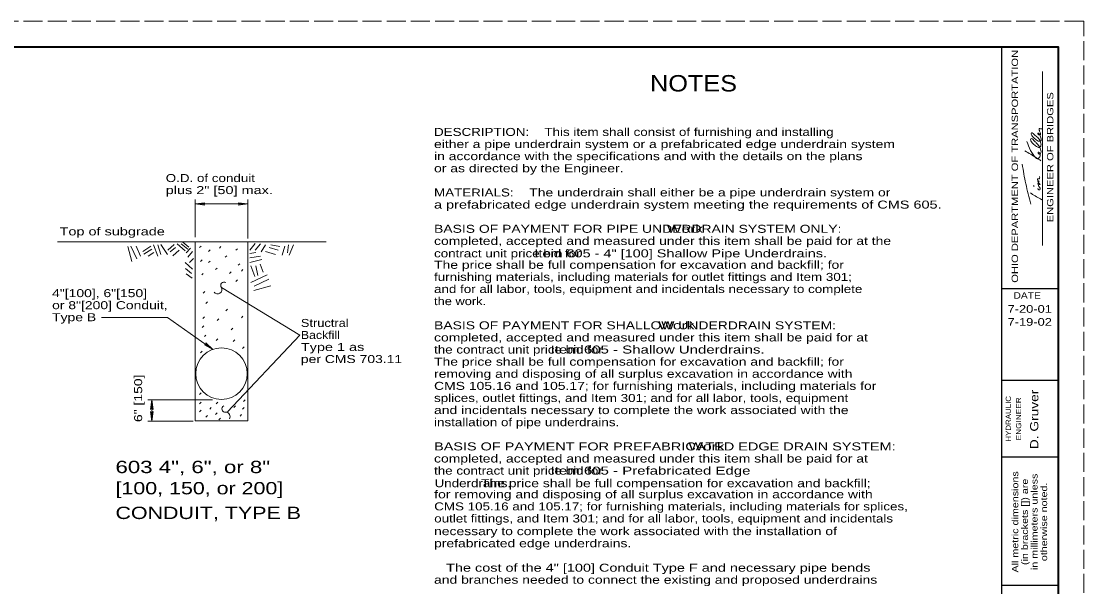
# Model space of a CAD drawing. Extents: x 743.9 to 777.9, y 1051 to 1073.
# Drawn here: x 757.15 to 777.86, y 1062 to 1073.02 of the extents above; entities that cross this region are included whole.
import ezdxf
from ezdxf.enums import TextEntityAlignment as Align

# ---------------------------------------------------------------- set-up
doc = ezdxf.new("R2010")
doc.units = 0
doc.header["$LTSCALE"] = 0.062
doc.linetypes.add('LONG_DASHED', pattern=[7.5, 6, -1.5])
doc.layers.add('1', color=7, linetype='Continuous', lineweight=13)
doc.layers.add('47', color=7, linetype='Continuous', lineweight=13)

msp = doc.modelspace()

# ---------------------------------------------------------------- linework, layer by layer
at = {"layer": '1', "lineweight": 25}
for p, q in [((745.86317, 1072.51808), (777.36317, 1072.51808)), ((776.26317, 1051.51808), (776.26317, 1072.51808)), ((777.36317, 1072.51808), (777.36317, 1051.51808)), ((777.36317, 1067.80225), (776.26317, 1067.80225)), ((777.36317, 1066.01808), (776.26317, 1066.01808)), ((777.36317, 1064.51808), (776.26317, 1064.51808)), ((777.36317, 1062.01808), (776.26317, 1062.01808))]:
    msp.add_line(p, q, dxfattribs=at)
at = {"layer": '1'}
for p, q in [((777.06192, 1068.64908), (777.06192, 1072.03917)), ((776.89442, 1069.8), (776.88425, 1069.81925)), ((760.54325, 1068.80992), (760.54325, 1069.54167)), ((761.56733, 1068.78375), (761.56733, 1069.54167)), ((760.54325, 1069.45808), (761.56733, 1069.45808)), ((757.85758, 1068.72042), (763.09308, 1068.72042)), ((760.54325, 1065.22875), (760.54325, 1068.72042)), ((761.56733, 1065.22875), (761.56733, 1068.72042)), ((759.31017, 1068.33375), (759.22658, 1068.6265)), ((759.40425, 1068.38608), (759.28925, 1068.63692)), ((759.47733, 1068.43833), (759.39375, 1068.63692)), ((759.67592, 1068.63692), (759.51917, 1068.53242)), ((759.69683, 1068.57425), (759.54008, 1068.48017)), ((759.73867, 1068.5115), (759.62367, 1068.43833)), ((759.81175, 1068.43833), (759.72817, 1068.65783)), ((759.8745, 1068.46967), (759.81175, 1068.65783)), ((759.99992, 1068.46967), (759.8745, 1068.66833)), ((760.13575, 1068.66833), (760.01033, 1068.55333)), ((760.15667, 1068.60558), (760.05217, 1068.52192)), ((760.22975, 1068.55333), (760.10442, 1068.44875)), ((760.34475, 1068.54283), (760.188, 1068.67875)), ((760.397, 1068.57425), (760.27158, 1068.67875)), ((760.41792, 1068.616), (760.30292, 1068.71017)), ((760.44925, 1068.59517), (760.36567, 1068.50108)), ((760.49108, 1068.53242), (760.397, 1068.41742)), ((760.65825, 1068.637), (760.62692, 1068.60558)), ((760.83592, 1068.56383), (760.80458, 1068.53242)), ((761.04492, 1068.6265), (761.01358, 1068.59508)), ((761.36892, 1068.58467), (761.33758, 1068.55325)), ((761.60925, 1068.55333), (761.71375, 1068.68925)), ((761.72417, 1068.5115), (761.60925, 1068.49058)), ((761.71375, 1068.55333), (761.81825, 1068.67875)), ((761.82867, 1068.52192), (761.91225, 1068.65783)), ((761.91225, 1068.53242), (762.11083, 1068.46967)), ((761.98542, 1068.60558), (762.16308, 1068.55333)), ((762.01675, 1068.65783), (762.19442, 1068.6265)), ((762.23625, 1068.45925), (762.2885, 1068.63692)), ((762.34075, 1068.50108), (762.36167, 1068.65783)), ((762.37208, 1068.45925), (762.45567, 1068.65783)), ((760.34475, 1068.31283), (760.49108, 1068.18742)), ((760.51192, 1068.3965), (760.42833, 1068.31283)), ((760.67917, 1068.36517), (760.64783, 1068.33375)), ((760.83592, 1068.34425), (760.80458, 1068.31283)), ((761.15992, 1068.44883), (761.12858, 1068.41742)), ((761.81825, 1068.43833), (761.60925, 1068.40692)), ((761.83917, 1068.37558), (761.60925, 1068.31283)), ((760.35517, 1068.19783), (760.47017, 1068.10375)), ((760.36567, 1068.09333), (760.48058, 1068.00967)), ((760.70008, 1068.10383), (760.66875, 1068.07242)), ((760.97175, 1068.20833), (760.94042, 1068.17692)), ((761.2435, 1068.13517), (761.21217, 1068.10375)), ((761.41067, 1068.292), (761.37933, 1068.26058)), ((761.47342, 1068.177), (761.44208, 1068.14558)), ((761.63008, 1068.25017), (761.70325, 1068.04108)), ((761.72417, 1068.25017), (761.766, 1068.062)), ((761.80775, 1068.2815), (761.8705, 1068.12467)), ((761.36892, 1067.97833), (761.33758, 1067.94692)), ((761.94367, 1068.07242), (761.63008, 1067.92608)), ((761.975, 1067.98875), (761.69283, 1067.85292)), ((760.73142, 1067.74833), (760.70008, 1067.71692)), ((762.01675, 1067.86333), (761.68242, 1067.76925)), ((760.78367, 1067.54975), (760.75233, 1067.51833)), ((761.17033, 1067.40342), (761.139, 1067.372)), ((761.47342, 1067.2675), (761.44208, 1067.23608)), ((758.7145, 1067.2465), (760.00467, 1067.2465)), ((760.88792, 1066.62292), (760.00467, 1067.2465)), ((760.7105, 1067.07933), (760.67917, 1067.04792)), ((760.721, 1067.257), (760.68967, 1067.22558)), ((761.00317, 1067.21517), (760.97183, 1067.18375)), ((760.75233, 1066.90158), (760.721, 1066.87017)), ((761.27483, 1067.0375), (761.2435, 1067.00608)), ((760.98225, 1066.82842), (760.95092, 1066.797)), ((761.31667, 1066.8075), (761.28533, 1066.77608)), ((761.49425, 1066.67158), (761.46292, 1066.64017)), ((760.67917, 1066.58792), (760.64783, 1066.5565)), ((760.88283, 1065.63917), (759.61842, 1065.63917)), ((759.69675, 1065.221), (759.69675, 1065.63917)), ((760.65825, 1065.7725), (760.62692, 1065.74108)), ((761.51517, 1065.63658), (761.48383, 1065.60517)), ((760.65825, 1065.59483), (760.62692, 1065.56342)), ((760.65825, 1065.438), (760.62692, 1065.40658)), ((760.85683, 1065.49025), (760.8255, 1065.45883)), ((760.98225, 1065.59483), (760.95092, 1065.56342)), ((761.32708, 1065.52158), (761.29575, 1065.49017)), ((761.49425, 1065.49025), (761.46292, 1065.45883)), ((760.50142, 1065.221), (759.61842, 1065.221)), ((760.54325, 1065.22875), (761.56733, 1065.22875)), ((760.78367, 1065.33342), (760.75233, 1065.302)), ((760.97175, 1065.38575), (760.94042, 1065.35433)), ((761.0345, 1065.28117), (761.00317, 1065.24975)), ((761.4475, 1065.34992), (761.41617, 1065.3185))]:
    msp.add_line(p, q, dxfattribs=at)
at = {"layer": '1', "linetype": 'LONG_DASHED'}
msp.add_lwpolyline([(743.86317, 1051.01808), (777.86317, 1051.01808), (777.86317, 1073.01808), (743.86317, 1073.01808)], close=True, dxfattribs=at)
at = {"layer": '1', "lineweight": 40}
msp.add_lwpolyline([(745.86317, 1072.51808), (777.36317, 1072.51808), (777.36317, 1051.51808), (745.86317, 1051.51808)], close=True, dxfattribs=at)
msp.add_lwpolyline([(745.86317, 1072.51808), (777.36317, 1072.51808), (777.36317, 1051.51808), (745.86317, 1051.51808)], close=True, dxfattribs=at)
at = {"layer": '1'}
msp.add_lwpolyline([(761.17033, 1065.40442), (762.58108, 1066.89942), (761.05533, 1067.82983)], dxfattribs=at)
msp.add_circle((761.05526, 1066.14873), 0.50287, dxfattribs=at)
for centre, radius, start, end in [((761.10242, 1067.87221), 0.06334, 54.7219, 221.98582), ((760.977, 1067.79089), 0.08748, 219.07128, 26.43546), ((761.12666, 1065.46198), 0.06334, 114.7219, 281.98582), ((761.13437, 1065.3127), 0.08748, 328.22199, 86.43546)]:
    msp.add_arc(centre, radius, start, end, dxfattribs=at)
for points in [[(776.755, 1070.67508), (776.93817, 1070.34675), (776.95333, 1070.33617), (776.9635, 1070.33617), (776.99542, 1070.35983), (777.0105, 1070.394), (777.0055, 1070.44525), (776.98858, 1070.46708), (776.97508, 1070.46708), (776.97333, 1070.45408), (776.9835, 1070.43892), (776.997, 1070.4305), (777.01208, 1070.4305), (777.02725, 1070.45208), (777.03067, 1070.47142), (777.02042, 1070.52675), (776.93817, 1070.64717), (776.89267, 1070.69183), (776.85575, 1070.72642), (776.83058, 1070.72858), (776.83233, 1070.69), (776.8575, 1070.65125), (776.92475, 1070.58892), (776.96683, 1070.5635), (777.0005, 1070.559), (777.02383, 1070.585), (777.03067, 1070.61917), (777.02558, 1070.64492), (776.99542, 1070.71808), (776.96517, 1070.75008), (776.90458, 1070.8035), (776.87592, 1070.82933), (776.84242, 1070.84458), (776.839, 1070.81658), (776.84908, 1070.79075), (776.90625, 1070.73083), (776.97692, 1070.68358), (777.02892, 1070.68592), (777.02725, 1070.74358), (777.01542, 1070.7865), (777.00208, 1070.81225), (776.99192, 1070.823), (776.9685, 1070.838), (776.97025, 1070.82092), (777.0055, 1070.79942), (777.02042, 1070.81017), (777.00733, 1070.86383), (776.99875, 1070.89175), (776.99542, 1070.90442), (776.99542, 1070.91725), (776.99542, 1070.92592), (777.02042, 1070.92375), (777.04583, 1070.92375)], [(776.71617, 1070.49283), (776.93992, 1070.35533), (777.02558, 1070.29967)], [(776.83242, 1069.45583), (776.73375, 1069.85108), (776.6625, 1070.23342)], [(776.9635, 1069.75475), (776.97175, 1069.74408), (777.00892, 1069.73117), (777.01367, 1069.76358), (776.98858, 1069.8), (776.97333, 1069.83625), (776.97333, 1069.8555), (776.98858, 1069.84925), (776.99875, 1069.83842), (777.00892, 1069.83408), (776.98525, 1069.86625), (776.97333, 1069.88125), (776.97025, 1069.89858), (776.99367, 1069.892), (776.98525, 1069.90067), (776.96008, 1069.9285), (776.97025, 1069.94367), (776.987, 1069.94567), (776.99542, 1069.94367), (777.0055, 1069.965), (776.99875, 1069.99292)], [(777.04758, 1069.54025), (776.84242, 1069.66025), (776.82683, 1069.67067)]]:
    msp.add_spline(points, degree=3, dxfattribs=at)
at = {"layer": '47'}
for points in [[(760.73075, 1069.43467), (760.54325, 1069.45808), (760.73075, 1069.4815)], [(761.37983, 1069.4815), (761.56733, 1069.45808), (761.37983, 1069.43467)], [(760.74825, 1066.75017), (760.88792, 1066.62292), (760.72125, 1066.71192)], [(759.67333, 1065.45167), (759.69675, 1065.63917), (759.72017, 1065.45167)], [(759.72017, 1065.4085), (759.69675, 1065.221), (759.67333, 1065.4085)]]:
    msp.add_lwpolyline(points, dxfattribs=at)
for centre, start, end in [((760.73076, 1069.45809), 90, 270), ((761.37983, 1069.45808), 270, 90), ((760.73474, 1066.73106), 234.77785, 54.77785), ((759.69674, 1065.40851), 180, 0), ((759.69676, 1065.45166), 0, 180)]:
    msp.add_arc(centre, 0.02342, start, end, dxfattribs=at)

# ---------------------------------------------------------------- texts
at = {"layer": '1'}
for s, height, width, p in [('OHIO DEPARTMENT OF TRANSPORTATION', 0.125, 1.3, (776.58308, 1070.19033)), ('ENGINEER OF BRIDGES', 0.125, 1.3, (777.27142, 1070.36712)), ('D. Gruver', 0.16, 1.25, (776.97775, 1065.25733)), ('HYDRAULIC', 0.1, 1.15, (776.44225, 1065.26917)), ('ENGINEER', 0.1, 1.2, (776.64317, 1065.26921)), ('All metric dimensions', 0.125, 1.25, (776.587, 1063.26017)), ('in millimeters unless', 0.125, 1.25, (776.962, 1063.26021)), ('(in brackets []) are', 0.125, 1.25, (776.7745, 1063.26017)), ('otherwise noted.', 0.125, 1.25, (777.1495, 1063.26017))]:
    msp.add_text(s, height=height, rotation=90, dxfattribs=dict(at, width=width)).set_placement(p, align=Align.CENTER)
for s, height, width, p in [('NOTES', 0.32, 1.15, (769.40908, 1071.64917)), ('DESCRIPTION:', 0.156, 1.25, (765.1985, 1070.78242)), ('This item shall consist of furnishing and installing', 0.156, 1.25, (767.34942, 1070.78242)), ('either a pipe underdrain system or a prefabricated edge underdrain system', 0.156, 1.3, (765.1985, 1070.54642)), ('in accordance with the specifications and with the details on the plans', 0.156, 1.3, (765.1985, 1070.31042)), ('or as directed by the Engineer.', 0.156, 1.3, (765.1985, 1070.07442)), ('O.D. of conduit', 0.156, 1.25, (759.9685, 1069.8835)), ('plus 2" [50] max.', 0.156, 1.35, (759.9685, 1069.64883)), ('MATERIALS:', 0.156, 1.25, (765.1985, 1069.6025)), ('The underdrain shall either be a pipe underdrain system or', 0.156, 1.3, (767.05383, 1069.60383)), ('a prefabricated edge underdrain system meeting the requirements of CMS 605.', 0.156, 1.35, (765.1985, 1069.3665)), ('Top of subgrade', 0.156, 1.35, (757.89942, 1068.84383)), ('BASIS OF PAYMENT FOR PIPE UNDERDRAIN SYSTEM ONLY:', 0.156, 1.3, (765.1985, 1068.89442)), ('                                                      Work ', 0.156, 1.45, (765.1985, 1068.89442)), ('completed, accepted and measured under this item shall be paid for at the', 0.156, 1.3, (765.1985, 1068.65842)), ('contract unit price bid for', 0.156, 1.25, (765.1985, 1068.41592)), ('                         Item 605 - 4" [100] Shallow Pipe Underdrains.', 0.156, 1.35, (765.1985, 1068.41592)), ('The price shall be full compensation for excavation and backfill; for', 0.156, 1.3, (765.1985, 1068.19283)), ('furnishing materials, including materials for outlet fittings and Item 301;', 0.156, 1.25, (765.1985, 1067.95683)), ('and for all labor, tools, equipment and incidentals necessary to complete', 0.156, 1.25, (765.1985, 1067.72083)), ('4"[100], 6"[150]', 0.156, 1.3, (757.753, 1067.64042)), ('or 8"[200] Conduit,', 0.156, 1.3, (757.753, 1067.40575)), ('the work.', 0.156, 1.2, (765.1985, 1067.48483)), ('Type B', 0.156, 1.3, (757.753, 1067.17108)), ('Structral', 0.156, 1.2, (762.602, 1067.05975)), ('BASIS OF PAYMENT FOR SHALLOW UNDERDRAIN SYSTEM:', 0.156, 1.3, (765.1985, 1067.01283)), ('                                                    Work', 0.156, 1.45, (765.1985, 1067.01283)), ('Backfill', 0.156, 1.15, (762.602, 1066.82508)), ('completed, accepted and measured under this item shall be paid for at', 0.156, 1.3, (765.1985, 1066.77683)), ('Type 1 as ', 0.156, 1.35, (762.602, 1066.59042)), ('the contract unit price bid for', 0.156, 1.25, (765.1985, 1066.54083)), ('                            Item 605 - Shallow Underdrains.', 0.156, 1.4, (765.1985, 1066.54083)), ('per CMS 703.11', 0.156, 1.3, (762.602, 1066.35575)), ('The price shall be full compensation for excavation and backfill; for', 0.156, 1.3, (765.1985, 1066.30483)), ('removing and disposing of all surplus excavation in accordance with', 0.156, 1.3, (765.1985, 1066.06883)), ('CMS 105.16 and 105.17; for furnishing materials, including materials for ', 0.156, 1.3, (765.1985, 1065.83283)), ('splices, outlet fittings, and Item 301; and for all labor, tools, equipment', 0.156, 1.25, (765.1985, 1065.59683)), ('and incidentals necessary to complete the work associated with the', 0.156, 1.3, (765.1985, 1065.36083)), ('installation of pipe underdrains.', 0.156, 1.25, (765.1985, 1065.12483)), ('BASIS OF PAYMENT FOR PREFABRICATED EDGE DRAIN SYSTEM:', 0.156, 1.35, (765.1985, 1064.65283)), ('                                                           Work', 0.156, 1.45, (765.1985, 1064.65283)), ('completed, accepted and measured under this item shall be paid for at', 0.156, 1.3, (765.1985, 1064.41683)), ('603 4", 6", or 8" ', 0.24, 1.35, (758.98875, 1064.21042)), ('the contract unit price bid for', 0.156, 1.25, (765.1985, 1064.18083)), ('                            Item 605 - Prefabricated Edge', 0.156, 1.4, (765.1985, 1064.18083)), ('[100, 150, or 200]', 0.24, 1.3, (758.98875, 1063.79675)), ('Underdrains.', 0.156, 1.25, (765.20858, 1063.93575)), ('            The price shall be full compensation for excavation and backfill;', 0.156, 1.3, (765.20858, 1063.93575)), ('for removing and disposing of all surplus excavation in accordance with', 0.156, 1.3, (765.20208, 1063.71992)), ('CONDUIT, TYPE B', 0.24, 1.3, (758.98875, 1063.3155)), ('CMS 105.16 and 105.17; for furnishing materials, including materials for splices, ', 0.156, 1.25, (765.20208, 1063.48392)), ('outlet fittings, and Item 301; and for all labor, tools, equipment and incidentals', 0.156, 1.25, (765.20208, 1063.24783)), ('necessary to complete the work associated with the installation of', 0.156, 1.3, (765.1985, 1063.00092)), ('prefabricated edge underdrains.', 0.156, 1.3, (765.1985, 1062.76492)), ('   The cost of the 4" [100] Conduit Type F and necessary pipe bends', 0.156, 1.35, (765.1985, 1062.28883)), ('and branches needed to connect the existing and proposed underdrains', 0.156, 1.3, (765.1985, 1062.05417))]:
    msp.add_text(s, height=height, dxfattribs=dict(at, width=width)).set_placement(p)
for s, height, width, p in [('DATE', 0.125, 1.2, (776.75987, 1067.61083)), ('7-20-01', 0.15, 1.25, (776.81021, 1067.33533)), ('7-19-02', 0.15, 1.25, (776.81021, 1067.08225))]:
    msp.add_text(s, height=height, dxfattribs=dict(at, width=width)).set_placement(p, align=Align.CENTER)
at = {"layer": '1', "width": 1.3}
msp.add_text('6" [150]', height=0.156, rotation=90, dxfattribs=at).set_placement((759.50875, 1065.20583))

doc.saveas('drawing.dxf')
